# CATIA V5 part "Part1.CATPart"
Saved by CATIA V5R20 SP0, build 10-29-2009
Part number: 裤衩楼
Material "Fabric 2"
Bounding box of the stored display mesh (mm): x -150 to 150, y -70 to 70, z -40 to 310
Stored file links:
  F:\新建文件夹 (2)\Part1.CATPart
  D:\CATIA VR20\win_b64\startup\materials\Catalog.CATMaterial
  D:\CATIA VR20\win_b64\startup\materials\brown_fabric_01.jpg
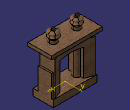
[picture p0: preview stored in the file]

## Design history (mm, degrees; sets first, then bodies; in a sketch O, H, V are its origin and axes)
Body1 (main body), material "Fabric 2"
  Sketch1 on xy-plane, origin (0, 0, 0), H (1, 0, 0), V (0, 1, 0)
    line L1 (120, 60) -> (120, -30)
    point P1 (120, 60)
    point P2 (-120, 60)
    line L2 (-120, 60) -> (-120, -30)
    spline S1 through (-120, 60) (0, 30) (120, 60)
    spline S2 through (-120, -30) (0, -60) (120, -30)
    point P3 (120, -30)
    point P4 (-120, -30)
    point P5 (-120, 60)
    point P6 (0, 30)
    point P7 (120, 60)
    point P8 (-120, -30)
    point P10 (120, -30)
    vertical: L1 V, L2 V
    coincidence: P5 P2, P6 V, P7 P1, P8 L2, P10 L1, P10 P3, P8 P4
  Sketch2 on xy-plane, origin (0, 0, 0), H (1, 0, 0), V (0, 1, 0)
    spline S1 through (-120, -30) (0, -60) (120, -30)
    point P1 (0, -60)
    coincidence: P1 V
  Sketch3 on xy-plane, origin (0, 0, 0), H (1, 0, 0), V (0, 1, 0)
  Sketch4 on xy-plane, origin (0, 0, 0), H (1, 0, 0), V (0, 1, 0)
  Pad1: profile Sketch1, direction (0, 0, 1), length 200
  Sketch5 on zx-plane, origin (0, 0, 0), H (-1, 0, 0), V (0, 0, 1)
    point P1 (0, 80)
    line L1 (70, 160) -> (70, 0)
    line L2 (70, 0) -> (-70, 0)
    line L3 (-70, 0) -> (-70, 160)
    line L4 (-70, 160) -> (70, 160)
    vertical: L1 V, L3 V
    horizontal: L2 H, L4 H
    equidistance: L1 L3 P1, L2 L4 P1
  Pocket1: profile Sketch5, direction (0, -1, 0), length 200
  Sketch6 on zx-plane, origin (0, 0, 0), H (-1, 0, 0), V (0, 0, 1)
    point P1 (0, 80)
    line L1 (70, 160) -> (70, 0)
    line L2 (70, 0) -> (-70, 0)
    line L3 (-70, 0) -> (-70, 160)
    line L4 (-70, 160) -> (70, 160)
    point P3 (70, 0)
    vertical: L1 V, L3 V
    horizontal: L2 H, L4 H
    equidistance: L1 L3 P1, L2 L4 P1
    coincidence: P3 H
  Pocket2: profile Sketch6, direction (0, 1, 0), length 200
  Plane1: type Offset, RefPlane start face of Pad1, Offset 20, reversed
  Sketch7 on Plane1, origin (0, 0, -20), H (1, 0, 0), V (0, 1, 0)
    circle A1 centre (70, 0) radius 28.2843
    point P1 (70, 0)
    coincidence: P1 H
  Pad2: profile Sketch7, direction (0, 0, 1), length 200
  Plane2: type Offset, RefPlane start face of Pad1, Offset 20, reversed
  Sketch8 on Plane2, origin (0, 0, -20), H (1, 0, 0), V (0, 1, 0)
    circle A1 centre (-70, 0) radius 22.3607
    point P1 (-70, 0)
    coincidence: P1 H
  Pad3: profile Sketch8, direction (0, 0, 1), length 200
  Sketch9 on xy-plane, origin (0, 0, 0), H (1, 0, 0), V (0, 1, 0)
    line L1 (130, 60) -> (130, -60)
    line L2 (130, -60) -> (-130, -60)
    line L3 (-130, -60) -> (-130, 60)
    line L4 (-130, 60) -> (130, 60)
    vertical: L1 V, L3 V
    horizontal: L2 H, L4 H
    equidistance: L1 L3 O, L2 L4 O
  Sketch10 on xy-plane, origin (0, 0, 0), H (1, 0, 0), V (0, 1, 0)
  Pad4: profile Sketch9, direction (0, 0, -1), length 40
  Sketch11 on xy-plane, origin (0, 0, 0), H (1, 0, 0), V (0, 1, 0)
    point P1 (130, 0)
    line L1 (140, 50) -> (140, -50)
    line L2 (140, -50) -> (120, -50)
    line L3 (120, -50) -> (120, 50)
    line L4 (120, 50) -> (140, 50)
    point P6 (-130, 0)
    line L5 (-120, 50) -> (-120, -50)
    line L6 (-120, -50) -> (-140, -50)
    line L7 (-140, -50) -> (-140, 50)
    line L8 (-140, 50) -> (-120, 50)
    coincidence: P1 H, P6 H
    vertical: L1 V, L3 V, L5 V, L7 V
    horizontal: L2 H, L4 H, L6 H, L8 H
    equidistance: L1 L3 P1, L2 L4 P1, L5 L7 P6, L6 L8 P6
  Pocket3: profile Sketch11, direction (0, 0, 1), length 130
  Sketch12 on xy-plane, origin (0, 0, 0), H (1, 0, 0), V (0, 1, 0)
    point P1 (130, 0)
    point P2 (-130, 0)
    point P3 (120, 0)
    point P4 (-120, 0)
    point P5 (-120, 10)
    line L1 (-110, 50) -> (-110, -30)
    line L2 (-110, -30) -> (-130, -30)
    line L3 (-130, -30) -> (-130, 50)
    line L4 (-130, 50) -> (-110, 50)
    point P10 (110, 10)
    line L5 (120, 50) -> (120, -30)
    line L6 (120, -30) -> (100, -30)
    line L7 (100, -30) -> (100, 50)
    line L8 (100, 50) -> (120, 50)
    point P12 (120, -30)
    coincidence: P1 H, P2 H, P3 H, P4 H, P12 L2
    vertical: L1 V, L3 V, L5 V, L7 V
    horizontal: L2 H, L4 H, L6 H, L8 H
    equidistance: L1 L3 P5, L2 L4 P5, L5 L7 P10, L6 L8 P10
  Pad5: profile Sketch12, direction (0, 0, 1), length 130
  Sketch13 on xy-plane, origin (0, 0, 0), H (1, 0, 0), V (0, 1, 0)
    point P1 (-120, 10)
    line L1 (-110, 50) -> (-110, -30)
    line L2 (-110, -30) -> (-130, -30)
    line L3 (-130, -30) -> (-130, 50)
    line L4 (-130, 50) -> (-110, 50)
    vertical: L1 V, L3 V
    horizontal: L2 H, L4 H
    equidistance: L1 L3 P1, L2 L4 P1
  Sketch14 on xy-plane, origin (0, 0, 0), H (1, 0, 0), V (0, 1, 0)
    point P1 (120, 10)
    line L1 (130, 50) -> (130, -30)
    line L2 (130, -30) -> (110, -30)
    line L3 (110, -30) -> (110, 50)
    line L4 (110, 50) -> (130, 50)
    vertical: L1 V, L3 V
    horizontal: L2 H, L4 H
    equidistance: L1 L3 P1, L2 L4 P1
  Pad6: profile Sketch14, direction (0, 0, 1), length 130
  Plane3: type Offset, RefPlane end face of Pad1, Offset 20, reversed
  Sketch15 on Plane3, origin (0, 0, 220), H (1, 0, 0), V (0, -1, 0)
    line L1 (150, 70) -> (150, -70)
    line L2 (150, -70) -> (-150, -70)
    line L3 (-150, -70) -> (-150, 70)
    line L4 (-150, 70) -> (150, 70)
    vertical: L1 V, L3 V
    horizontal: L2 H, L4 H
    equidistance: L1 L3 O, L2 L4 O
  Pad7: profile Sketch15, direction (0, 0, 1), length 20
  Sketch16 on Plane1, origin (0, 0, -20), H (1, 0, 0), V (0, 1, 0)
    circle A1 centre (-70, 0) radius 22.3607
    point P1 (-70, 0)
    circle A2 centre (70, 0) radius 22.3607
    point P2 (70, 0)
    coincidence: P1 H, P2 H
  Pad8: profile Sketch16, direction (0, 0, 1), length 240
  Plane4: type Offset, RefPlane end face of Pad7, Offset 0, reversed
  Sketch17 on Plane4, origin (0, 0, 240), H (1, 0, 0), V (0, -1, 0)
    circle A1 centre (70, 0) radius 22.3607
    circle A2 centre (-70, 0) radius 22.3607
  Plane5: type Offset, RefPlane Plane4, Offset 10, reversed
  Plane6: type Offset, RefPlane Plane5, Offset 10, reversed
  Plane7: type Offset, RefPlane Plane6, Offset 10, reversed
  Plane8: type Offset, RefPlane Plane7, Offset 10, reversed
  Plane9: type Offset, RefPlane Plane8, Offset 10, reversed
  Pad9: profile Sketch17, direction (0, 0, 1), length 20
  Plane10: type Offset, RefPlane Plane7, Offset 10
  Plane11: type Offset, RefPlane end face of Pad9, Offset 10, reversed
  Plane12: type Offset, RefPlane end face of Pad9, Offset 10, reversed
  Sketch18 on Plane12, origin (0, 0, 270), H (1, 0, 0), V (0, -1, 0)
    circle A1 centre (-70.6473, 0) radius 28.964
    point P1 (-70.6473, 0)
    coincidence: P1 H
  Sketch19 on Plane11, origin (0, 0, 270), H (1, 0, 0), V (0, -1, 0)
    circle A1 centre (69.2591, 0) radius 30.0419
    point P1 (69.2591, 0)
    coincidence: P1 H
  Plane13: type Offset, RefPlane Plane12, Offset 10, reversed
  Plane14: type Offset, RefPlane Plane13, Offset 10, reversed
  Sketch20 on Plane13, origin (0, 0, 280), H (1, 0, 0), V (0, -1, 0)
    circle A1 centre (-70.9448, 0) radius 19.0182
    point P1 (-70.9448, 0)
    coincidence: P1 H
  Sketch21 on Plane14, origin (0, 0, 290), H (1, 0, 0), V (0, -1, 0)
    circle A1 centre (-71.0247, 0) radius 28.9801
    point P1 (-71.0247, 0)
    coincidence: P1 H
  Plane15: type Offset, RefPlane Plane14, Offset 10, reversed
  Sketch22 on Plane15, origin (0, 0, 300), H (1, 0, 0), V (0, -1, 0)
    circle A1 centre (-69.5929, 0) radius 11.661
    point P1 (-69.5929, 0)
    coincidence: P1 H
  Plane16: type Offset, RefPlane Plane11, Offset 10, reversed
  Plane17: type Offset, RefPlane Plane16, Offset 10, reversed
  Plane18: type Offset, RefPlane Plane17, Offset 10, reversed
  Sketch23 on Plane16, origin (0, 0, 280), H (1, 0, 0), V (0, -1, 0)
    circle A1 centre (69.1958, 0) radius 20.5192
    point P1 (69.1958, 0)
    coincidence: P1 H
  Sketch24 on Plane17, origin (0, 0, 290), H (1, 0, 0), V (0, -1, 0)
    circle A1 centre (69.2303, 0) radius 30.8828
    point P1 (69.2303, 0)
    coincidence: P1 H
  Sketch25 on Plane18, origin (0, 0, 300), H (1, 0, 0), V (0, -1, 0)
    circle A1 centre (69.9235, 0) radius 10.8124
    point P1 (69.9235, 0)
    coincidence: P1 H
  Loft1: solid, Sections (Sketch19; Sketch23; Sketch24; Sketch25)
  Loft2: solid, Sections (Sketch18; Sketch20; Sketch21; Sketch22)
  Plane19: type Offset, RefPlane Plane15, Offset 10, reversed
  Sketch26 on Plane19, origin (0, 0, 310), H (1, 0, 0), V (0, -1, 0)
    circle A1 centre (-70.1003, 0) radius 6.2717
    point P1 (-70.1003, 0)
    coincidence: P1 H
  Pad10: profile Sketch26, direction (0, 0, -1), length 150
  Plane20: type Offset, RefPlane Plane18, Offset 10, reversed
  Sketch27 on Plane20, origin (0, 0, 310), H (1, 0, 0), V (0, -1, 0)
    circle A1 centre (70.6162, 0) radius 6.267
    point P1 (70.6162, 0)
    coincidence: P1 H
  Pad11: profile Sketch27, direction (0, 0, -1), length 150
  Plane21: type Offset, RefPlane face of Pad7 from Sketch15.L4, Offset 10, reversed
